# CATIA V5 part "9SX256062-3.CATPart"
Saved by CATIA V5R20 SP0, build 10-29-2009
Part number: 9SX256062-3
Revision: ANY
Definition: UNKNOWN
Nomenclature: 9SX256062-3
Source: Unknown
Bounding box of the stored display mesh (mm): x -19.5 to 19.5, y -19.5 to 19.5, z -28 to 85
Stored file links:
  C:\Users\Utente\Desktop\IO LAVORO\3D X SITO CF\CUMSA\3D files SX.256062\SX 256062\9SX256062-3.CATPart
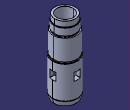
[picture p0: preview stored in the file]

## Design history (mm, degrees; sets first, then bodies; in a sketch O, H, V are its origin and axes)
Body1 "Chaflán9" (main body)
  Solid1: solid without history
